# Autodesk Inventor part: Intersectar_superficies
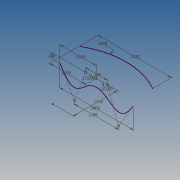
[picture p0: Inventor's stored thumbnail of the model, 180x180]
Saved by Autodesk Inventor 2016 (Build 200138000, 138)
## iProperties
Created: 2015-09
Part Number: Intersectar_superficies
Material: Generic
Document SubType Name: Modeling
Designer: julian.chica
Density: 1 g/cm^3
Appearance: Default
Author: julian.chica
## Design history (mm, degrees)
sketch "CURVA 1"
  geometry: L1 (1000, -140)-(600, -824.243); L2 (600, -824.243)-(300, 0); L3 (300, 0)-(-300, 0); L4 (-300, 0)-(-600, -824.243); L5 (-600, -824.243)-(-1000, -140); 2 further points
  constraints: 3 horizontal alignment, 1 coincident, 1 midpoint, 3 other
  dimensions: "d0" = 2000 distance of L5.end L1.start; "d1" = 1000 horizontal distance of L1.start point (0, 0); "d2" = 600 distance of L2.end L3.end; "d3" = 1200 distance of L1.end L4.end; "d4" = 110 deg angle of L3 L2; "d5" = 110 deg angle of L4 L3; "d6" = 140 vertical distance of point (0, 0) L1.start
sketch "CURVA 2"
  geometry: A1 r 2000 centre (0, -1200) between (1000, 532.051) and (-1000, 532.051); 1 further point
  constraints: 2 point on circle, 1 centre point, 1 vertical alignment
  dimensions: "d7" = 2000 distance of A1.start A1.end; "d8" = 1200 distance of point (0, 0) A1.centre; "d9" = 1000 horizontal distance of point (0, 0) A1.end; "d11" = 2000 radius of A1
